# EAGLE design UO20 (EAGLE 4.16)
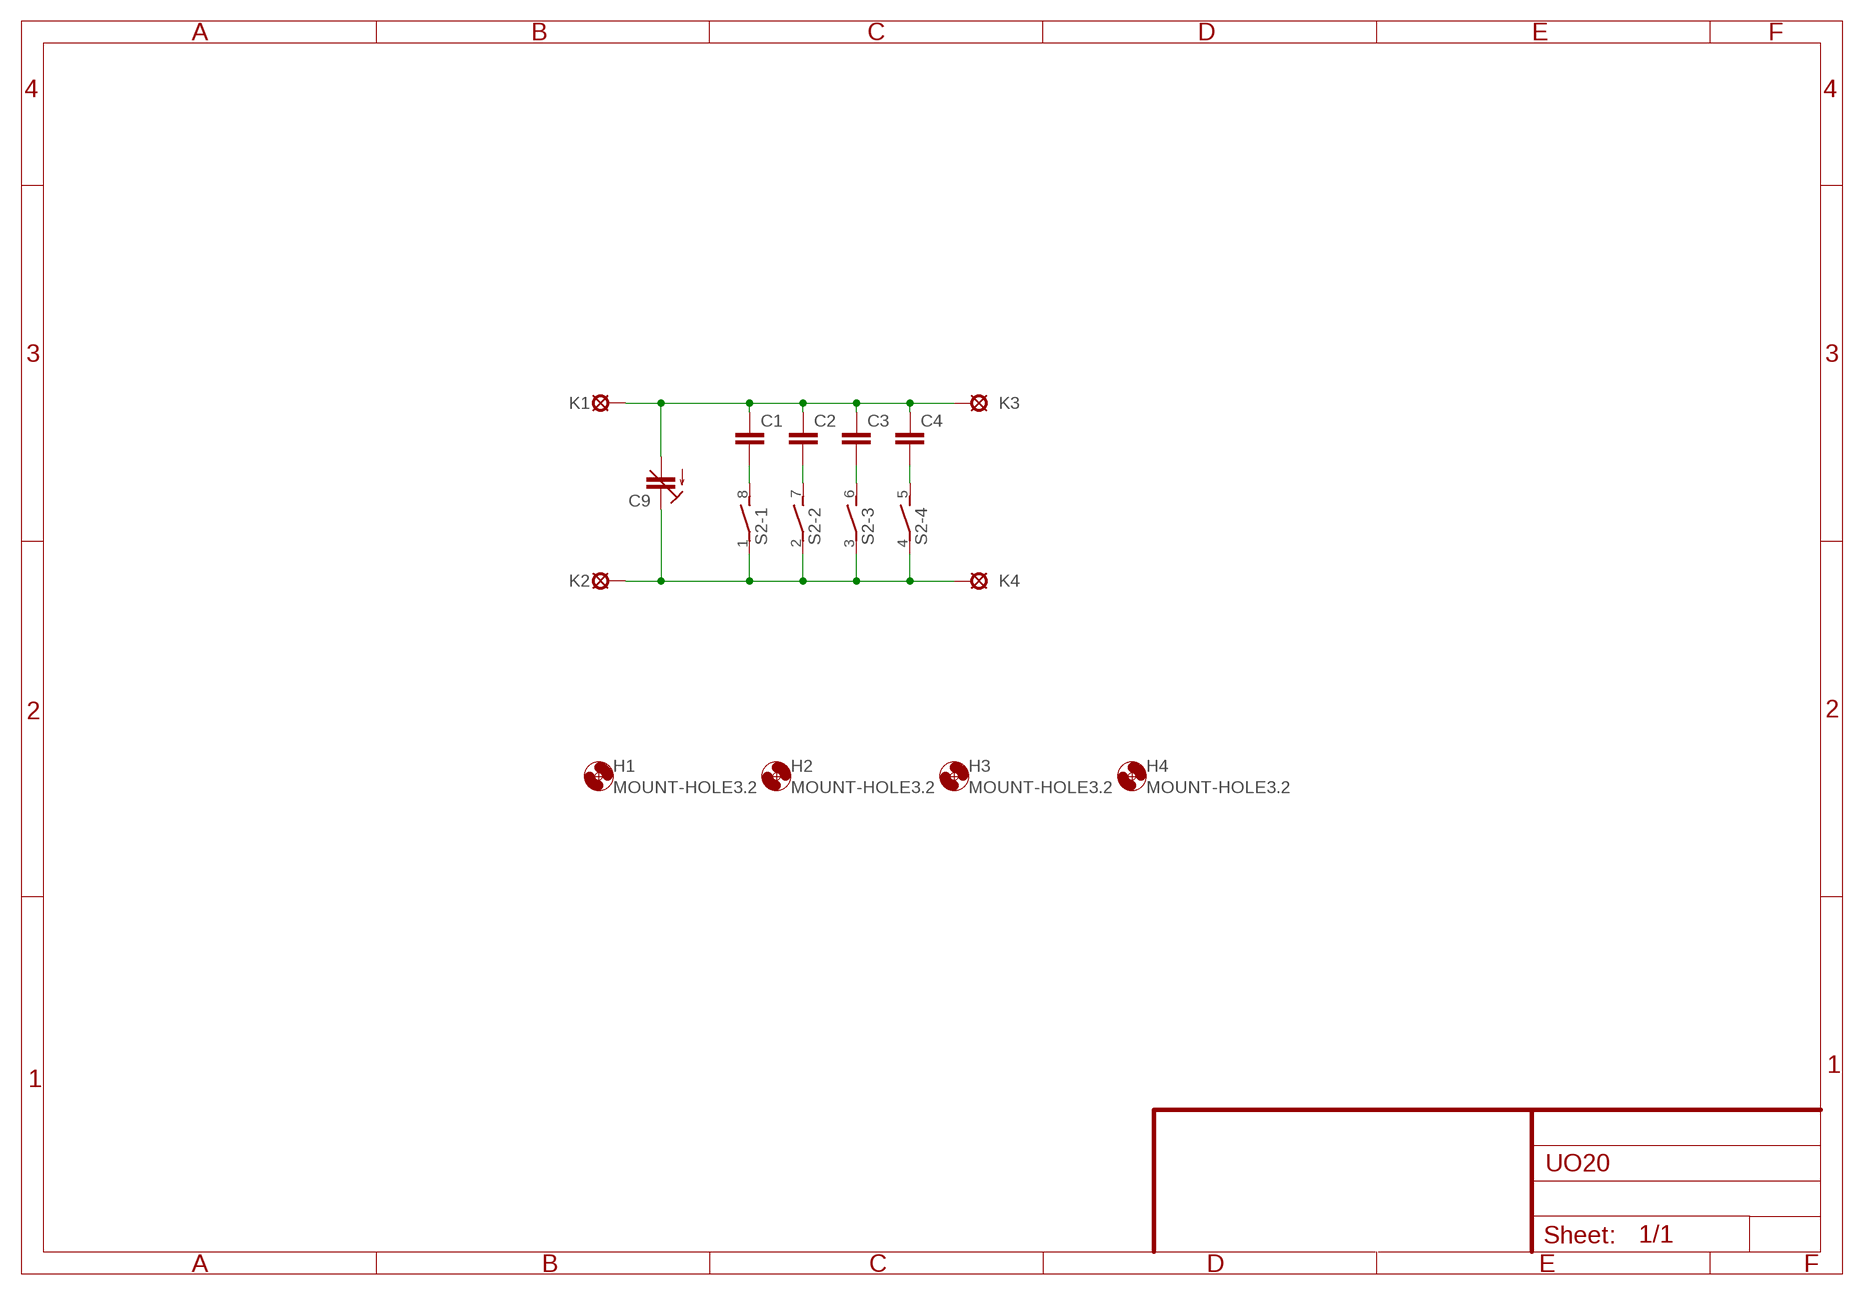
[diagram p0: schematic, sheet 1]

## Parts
C1  C-EU050-075X075  [C050-075X075]
C2  C-EU050-075X075  [C050-075X075]
C3  C-EU050-075X075  [C050-075X075]
C4  C-EU050-075X075  [C050-075X075]
C9  C-TRIMM808  [CTRIM808-BC]
H1  MOUNT-HOLE3.2  [3,2]
H2  MOUNT-HOLE3.2  [3,2]
H3  MOUNT-HOLE3.2  [3,2]
H4  MOUNT-HOLE3.2  [3,2]
K1  SE13  [SE13]
K2  SE13  [SE13]
K3  SE13  [SE13]
K4  SE13  [SE13]
S2  DIP04S  [DIP04S]

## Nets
N$1: C9.1(E) K2.MP K4.MP S2.1 S2.2 S2.3 S2.4
N$6: C4.2 S2.5
N$7: C3.2 S2.6
N$8: C2.2 S2.7
N$9: C1.2 S2.8
N$18: C1.1 C2.1 C3.1 C4.1 C9.2(A) K1.MP K3.MP

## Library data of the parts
C1-C4 = rcl:C-EU: CAPACITOR, European symbol
C9 = rcl:C-TRIMM: Trimm capacitor
H1-H4 = holes:MOUNT-HOLE: MOUNTING HOLE with drill center marker
K1-K4 = solpad:SE13: SOLDER PAD
S2 = switch-dil:DIP04S: DIL/CODE SWITCH

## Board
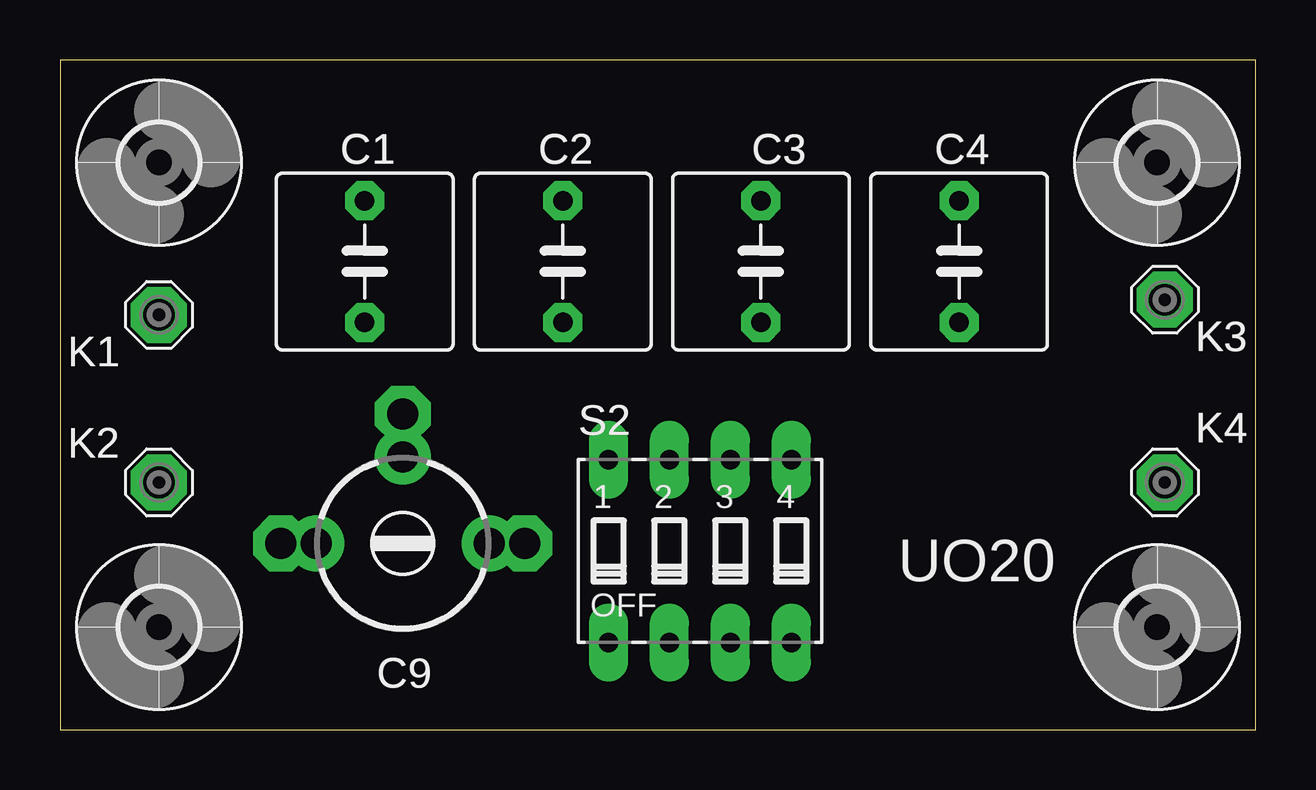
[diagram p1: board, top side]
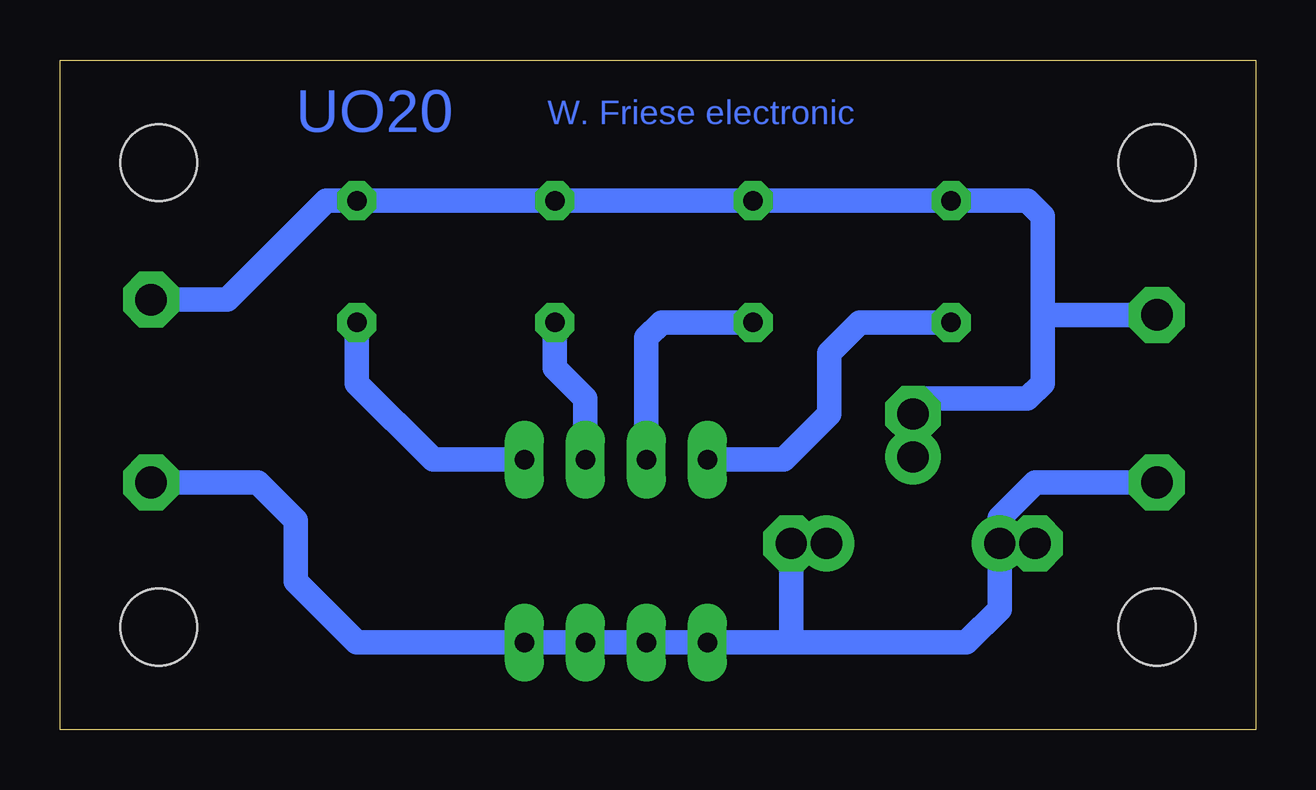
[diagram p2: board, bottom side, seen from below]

Size 49.83 x 27.93 mm. Coordinates in mm from the lower left corner, seen from the top.
Outline: 0,0 49.83,0 49.83,27.93 0,27.93 0,0
Copper layers 16: Bottom 0.035mm
Design rules "default": minimum track width 10mil, minimum drill 24mil, track to track 8mil, track to pad 8mil, pad to pad 8mil, via to via 8mil, smd to smd 8mil, copper to edge 40mil, drill to drill 8mil, minimum pad ring 10mil, minimum via ring 8mil, stop-mask expansion 0mil, vias tented up to drill 0mil, thermal gap 10mil

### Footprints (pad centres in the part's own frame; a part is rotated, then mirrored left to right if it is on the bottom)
C050-075X075 = drill 0.813 octagon: 1 -2.54,0; 2 2.54,0
CTRIM808-BC = drill 1.3 round: 1 -3.607,0; 2 0,3.607; 3 3.607,0
3,2 = hole 3.2: 0,0
SE13 = drill 1.321 pad 2.159 octagon: MP 0,0
DIP04S = drill 0.813 long: 1 -3.81,-3.81; 2 -1.27,-3.81; 3 1.27,-3.81; 4 3.81,-3.81; 5 3.81,3.81; 6 1.27,3.81; 7 -1.27,3.81; 8 -3.81,3.81

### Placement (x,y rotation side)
C1  12.69,19.52 270 top
C2  20.95,19.52 270 top
C3  29.21,19.52 270 top
C4  37.46,19.52 270 top
C9  14.28,7.77 0 top
H1  45.71,4.28 0 top
H2  45.71,23.65 0 top
H3  4.12,4.28 0 top
H4  4.12,23.65 0 top
K1  4.12,17.3 0 top
K2  4.12,10.31 0 top
K3  46.03,17.93 0 top
K4  46.03,10.31 0 top
S2  26.67,7.46 0 top

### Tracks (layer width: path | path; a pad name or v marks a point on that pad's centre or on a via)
N$1  (via drill 1.3)
  Bottom 1.016: 18.09,7.77 v19.36,7.77 19.36,3.65 | 19.36,3.65 12.06,3.65 10.68,5.03 C9.1 10.68,8.84 9.2,10.31 K2.MP | 19.36,3.65 S2.1 S2.2 S2.3 S2.4 37.46,3.65 40,6.18 40,8.73 41.59,10.31 K4.MP
N$2  (via drill 1.3)
  Bottom 1.016: v9.2,7.77 10.79,7.77
N$6
  Bottom 1.016: S2.5 34.28,11.27 37.46,14.44 C4.2
N$7
  Bottom 1.016: C3.2 29.21,15.08 27.94,13.81 S2.6
N$8
  Bottom 1.016: C2.2 24.76,16.98 25.39,16.35 S2.7
N$9
  Bottom 1.016: C1.2 16.51,16.98 17.78,15.71 17.78,13.17 19.68,11.27 S2.8
N$18  (via drill 1.3)
  Bottom 1.016: K3.MP 42.86,17.93 38.73,22.06 C4.1 C3.1 C2.1 C1.1 9.52,22.06 8.88,21.43 8.88,16.98 | C9.2 v14.28,13.17 14.28,13.49 13.96,13.81 9.52,13.81 8.88,14.44 8.88,16.98 | K1.MP 8.57,17.3 8.88,16.98

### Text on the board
Bottom: W. Friese electronic | UO20
tPlace: UO20
_tNames: C1 | C2 | C3 | C4 | K3 | K1 | S2 | K4 | K2 | C9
